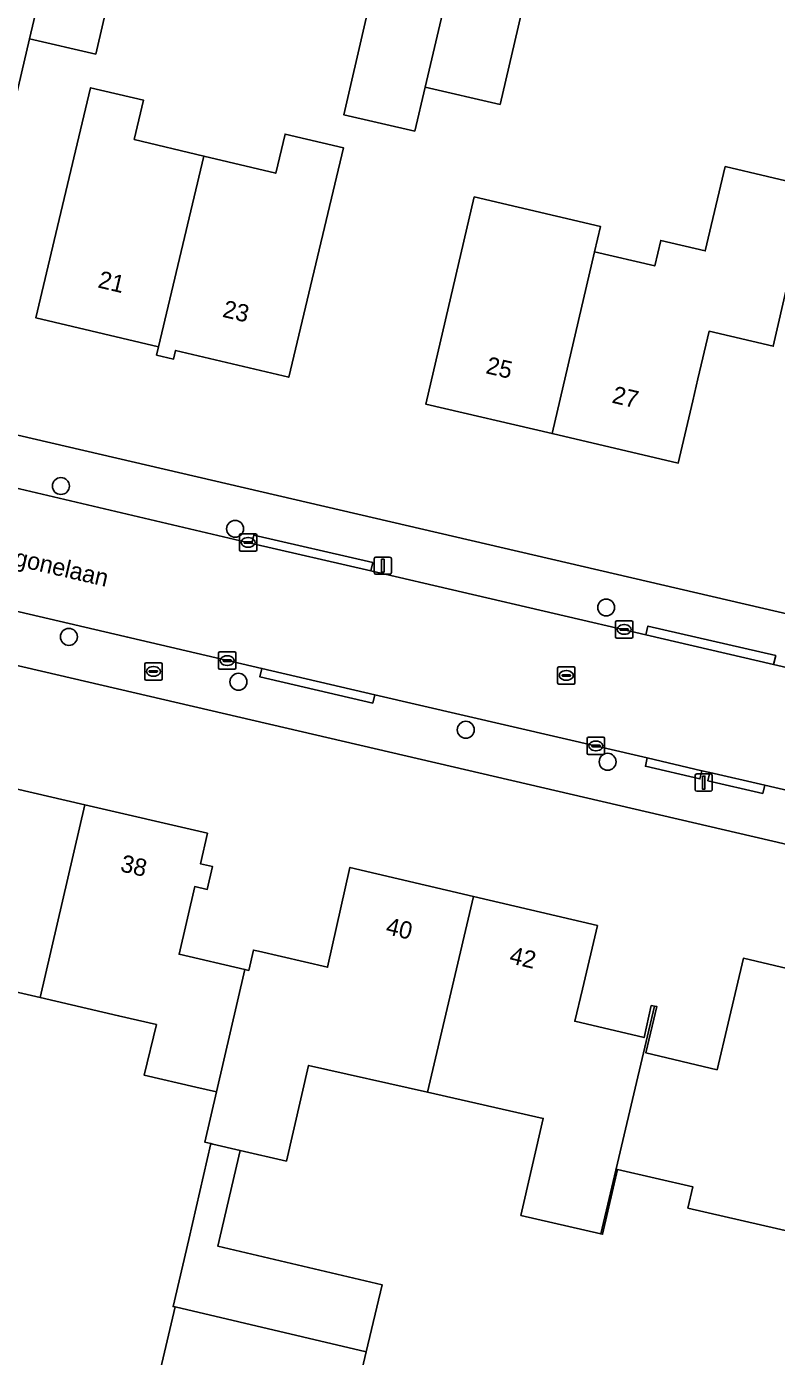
# Model space of a CAD drawing. Extents: x 162184 to 163154, y 385507 to 386516.
# Drawn here: x 162630.3 to 162673.6, y 385878.1 to 385954.9 of the extents above; entities that cross this region are included whole.
import ezdxf

# ---------------------------------------------------------------- set-up
doc = ezdxf.new("R2010")
doc.units = 0
for name, color, linetype in [('IMGEO_Boom', 7, 'Continuous'), ('IMGEO_Brandkraan', 7, 'Continuous'), ('IMGEO_Erf', 7, 'Continuous'), ('IMGEO_Kolk', 7, 'Continuous'), ('IMGEO_Lichtmast', 7, 'Continuous'), ('IMGEO_Openbare_ruimte_label', 7, 'Continuous'), ('IMGEO_Pand', 7, 'Continuous'), ('IMGEO_Pand_nummerreeks', 7, 'Continuous'), ('IMGEO_Rijbaan_lokaal_open', 7, 'Continuous'), ('IMGEO_Rioolput', 7, 'Continuous'), ('IMGEO_Voetpad_open', 7, 'Continuous')]:
    doc.layers.add(name, color=color, linetype=linetype)

msp = doc.modelspace()

# ---------------------------------------------------------------- linework, layer by layer
at = {"layer": 'IMGEO_Boom'}
for centre in [(162632.267, 385928.363), (162642.328, 385925.887), (162663.761, 385921.341), (162632.729, 385919.642), (162642.52, 385917.05), (162655.653, 385914.276), (162663.847, 385912.426)]:
    msp.add_circle(centre, 0.489, dxfattribs=at)
at = {"layer": 'IMGEO_Brandkraan'}
for p, q in [((162637.108, 385917.221), (162637.108, 385918.073)), ((162637.183, 385918.147), (162638.035, 385918.147)), ((162637.367, 385917.641), (162637.367, 385917.653)), ((162637.805, 385917.604), (162637.407, 385917.604)), ((162637.41, 385917.69), (162637.808, 385917.69)), ((162637.596, 385917.927), (162637.621, 385917.927)), ((162637.851, 385917.653), (162637.851, 385917.641)), ((162638.109, 385918.073), (162638.109, 385917.221)), ((162638.035, 385917.147), (162637.183, 385917.147)), ((162637.619, 385917.367), (162637.594, 385917.367))]:
    msp.add_line(p, q, dxfattribs=at)
for points in [[(162637.108, 385917.221), (162637.108, 385918.073)], [(162637.183, 385918.147), (162638.035, 385918.147)], [(162638.109, 385918.073), (162638.109, 385917.221)], [(162638.035, 385917.147), (162637.183, 385917.147)]]:
    msp.add_lwpolyline(points, dxfattribs=at)
for centre, radius, start, end in [((162637.185, 385918.071), 0.0765, 91.55205, 178.44795), ((162637.185, 385918.071), 0.0765, 91.55205, 178.44795), ((162637.407, 385917.65), 0.0403, 85.87752, 175.75265), ((162637.404, 385917.64), 0.0366, 178.93798, 274.71019), ((162637.808, 385917.647), 0.043, 264.86636, 352.45326), ((162637.812, 385917.652), 0.0386, 1.73085, 96.63898), ((162638.033, 385918.071), 0.0765, 1.55205, 88.44795), ((162638.033, 385918.071), 0.0765, 1.55205, 88.44795), ((162637.185, 385917.223), 0.0765, 181.55205, 268.44795), ((162637.185, 385917.223), 0.0765, 181.55205, 268.44795), ((162638.033, 385917.223), 0.0765, 271.55205, 358.44795), ((162638.033, 385917.223), 0.0765, 271.55205, 358.44795)]:
    msp.add_arc(centre, radius, start, end, dxfattribs=at)
for centre, major_axis, ratio, start_param, end_param in [((162637.595, 385917.647), (-0.387, 0.002), 0.722429, 4.712389, 7.853982), ((162637.62, 385917.647), (-0.39, 0.002), 0.717154, 1.570796, 4.712389)]:
    msp.add_ellipse(centre, major_axis=major_axis, ratio=ratio, start_param=start_param, end_param=end_param, dxfattribs=at)
at = {"layer": 'IMGEO_Erf'}
for points in [[(162631.269, 385957.737), (162627.989, 385958.519), (162629.646, 385965.47), (162629.445, 385965.517), (162627.833, 385958.556), (162625.653, 385949.215), (162625.766, 385949.188), (162625.597, 385948.48), (162628.926, 385947.687), (162630.448, 385954.213)], [(162659.52, 385958.55), (162657.637, 385950.422), (162653.306, 385951.425), (162652.706, 385948.878), (162648.607, 385949.827), (162651.08, 385960.505), (162655.219, 385959.546)], [(162677.484, 385954.19), (162683.364, 385952.8), (162682.951, 385951.053), (162682.096, 385951.255), (162680.348, 385943.861), (162681.453, 385943.599), (162681.163, 385942.376), (162675.102, 385943.81), (162673.411, 385936.441), (162669.703, 385937.308), (162669.061, 385934.562), (162668.765, 385933.296), (162667.923, 385929.693), (162660.635, 385931.396), (162653.345, 385933.1), (162654.483, 385937.969), (162656.144, 385945.073), (162663.43, 385943.37), (162663.086, 385941.898), (162666.567, 385941.084), (162666.911, 385942.556), (162669.488, 385941.953), (162670.644, 385946.832), (162675.53, 385945.674)], [(162636.498, 385948.396), (162640.529, 385947.435), (162644.671, 385946.442), (162645.212, 385948.71), (162648.592, 385947.904), (162646.589, 385939.51), (162645.429, 385934.646), (162638.891, 385936.206), (162638.77, 385935.701), (162637.79, 385935.934), (162637.902, 385936.403), (162630.812, 385938.094), (162631.972, 385942.958), (162633.983, 385951.389), (162637.038, 385950.66)]]:
    msp.add_lwpolyline(points, close=True, dxfattribs=at)
for points in [[(162636.708, 385963.834), (162634.274, 385953.326), (162630.448, 385954.213), (162628.926, 385947.687), (162625.597, 385948.48), (162625.226, 385946.922), (162624.067, 385942.058), (162623.062, 385942.297), (162622.522, 385940.031), (162615.44, 385941.718), (162608.362, 385943.404), (162608.894, 385945.636), (162607.824, 385945.892), (162608.983, 385950.756), (162609.465, 385952.777), (162609.699, 385953.758), (162610.448, 385956.905)], [(162535.867, 385953.127), (162747.115, 385904.027), (162750.77, 385903.177)], [(162742.31, 385891.809), (162533.141, 385940.448)], [(162626.577, 385911.571), (162633.653, 385909.93), (162640.729, 385908.289), (162640.321, 385906.529), (162641.027, 385906.365), (162640.72, 385905.041), (162640, 385905.208), (162639.093, 385901.299), (162642.899, 385900.417), (162643.115, 385900.367), (162643.387, 385901.539), (162643.682, 385901.471), (162647.671, 385900.547), (162648.96, 385906.32), (162656.108, 385904.635), (162663.253, 385902.951), (162662.388, 385899.277), (162661.952, 385897.428), (162665.951, 385896.486), (162666.369, 385898.334), (162666.554, 385898.3), (162666.691, 385898.274), (162666.06, 385895.594), (162670.174, 385894.625), (162670.806, 385897.306), (162671.692, 385901.065), (162678.528, 385899.454)], [(162637.027, 385873.14), (162638.858, 385880.909), (162638.747, 385880.935), (162639.646, 385884.81), (162640.931, 385890.354), (162640.584, 385890.435), (162641.257, 385893.337), (162640.064, 385893.614), (162637.082, 385894.305), (162637.783, 385897.233), (162635.601, 385897.739), (162631.071, 385898.789), (162626.359, 385899.882)], [(162674.784, 385885.176), (162668.484, 385886.628), (162668.767, 385887.856), (162664.423, 385888.858), (162663.559, 385885.109), (162663.453, 385885.133), (162658.836, 385886.199), (162660.131, 385891.812), (162653.442, 385893.324), (162646.576, 385894.876), (162645.293, 385889.343), (162642.617, 385889.963), (162641.331, 385884.415), (162650.818, 385882.191), (162649.904, 385878.319), (162648.723, 385873.317)]]:
    msp.add_lwpolyline(points, dxfattribs=at)
at = {"layer": 'IMGEO_Kolk'}
for p, q in [((162642.58, 385924.676), (162642.58, 385925.528)), ((162642.655, 385925.602), (162643.507, 385925.602)), ((162642.882, 385925.145), (162643.28, 385925.145)), ((162643.068, 385925.382), (162643.093, 385925.382)), ((162643.581, 385925.528), (162643.581, 385924.676)), ((162643.507, 385924.602), (162642.655, 385924.602)), ((162642.839, 385925.096), (162642.839, 385925.108)), ((162643.277, 385925.059), (162642.879, 385925.059)), ((162643.091, 385924.822), (162643.066, 385924.822)), ((162643.323, 385925.108), (162643.323, 385925.096)), ((162664.302, 385919.645), (162664.302, 385920.497)), ((162664.377, 385920.571), (162665.229, 385920.571)), ((162665.303, 385920.497), (162665.303, 385919.645)), ((162664.561, 385920.065), (162664.561, 385920.077)), ((162664.999, 385920.028), (162664.601, 385920.028)), ((162664.604, 385920.114), (162665.002, 385920.114)), ((162664.813, 385919.791), (162664.788, 385919.791)), ((162664.79, 385920.351), (162664.815, 385920.351)), ((162665.045, 385920.077), (162665.045, 385920.065)), ((162665.229, 385919.571), (162664.377, 385919.571)), ((162641.374, 385917.846), (162641.374, 385918.698)), ((162641.449, 385918.772), (162642.301, 385918.772)), ((162641.633, 385918.266), (162641.633, 385918.278)), ((162642.071, 385918.229), (162641.673, 385918.229)), ((162641.676, 385918.315), (162642.074, 385918.315)), ((162641.862, 385918.552), (162641.887, 385918.552)), ((162642.117, 385918.278), (162642.117, 385918.266)), ((162642.375, 385918.698), (162642.375, 385917.846)), ((162642.301, 385917.772), (162641.449, 385917.772)), ((162641.885, 385917.992), (162641.86, 385917.992)), ((162662.668, 385912.914), (162662.668, 385913.766)), ((162662.743, 385913.84), (162663.595, 385913.84)), ((162663.156, 385913.62), (162663.181, 385913.62)), ((162663.669, 385913.766), (162663.669, 385912.914)), ((162663.595, 385912.84), (162662.743, 385912.84)), ((162662.927, 385913.334), (162662.927, 385913.346)), ((162663.365, 385913.297), (162662.967, 385913.297)), ((162662.97, 385913.383), (162663.368, 385913.383)), ((162663.179, 385913.06), (162663.154, 385913.06)), ((162663.411, 385913.346), (162663.411, 385913.334))]:
    msp.add_line(p, q, dxfattribs=at)
for points in [[(162642.58, 385924.676), (162642.58, 385925.528)], [(162642.655, 385925.602), (162643.507, 385925.602)], [(162643.581, 385925.528), (162643.581, 385924.676)], [(162643.507, 385924.602), (162642.655, 385924.602)], [(162664.302, 385919.645), (162664.302, 385920.497)], [(162664.377, 385920.571), (162665.229, 385920.571)], [(162665.303, 385920.497), (162665.303, 385919.645)], [(162665.229, 385919.571), (162664.377, 385919.571)], [(162641.374, 385917.846), (162641.374, 385918.698)], [(162641.449, 385918.772), (162642.301, 385918.772)], [(162642.375, 385918.698), (162642.375, 385917.846)], [(162642.301, 385917.772), (162641.449, 385917.772)], [(162662.668, 385912.914), (162662.668, 385913.766)], [(162662.743, 385913.84), (162663.595, 385913.84)], [(162663.669, 385913.766), (162663.669, 385912.914)], [(162663.595, 385912.84), (162662.743, 385912.84)]]:
    msp.add_lwpolyline(points, dxfattribs=at)
for centre, radius, start, end in [((162642.657, 385925.526), 0.0765, 91.55205, 178.44795), ((162642.657, 385925.526), 0.0765, 91.55205, 178.44795), ((162642.879, 385925.105), 0.0403, 85.87752, 175.75265), ((162643.284, 385925.107), 0.0386, 1.73085, 96.63898), ((162643.505, 385925.526), 0.0765, 1.55205, 88.44795), ((162643.505, 385925.526), 0.0765, 1.55205, 88.44795), ((162642.657, 385924.678), 0.0765, 181.55205, 268.44795), ((162642.657, 385924.678), 0.0765, 181.55205, 268.44795), ((162642.876, 385925.095), 0.0366, 178.93798, 274.71019), ((162643.28, 385925.102), 0.043, 264.86636, 352.45326), ((162643.505, 385924.678), 0.0765, 271.55205, 358.44795), ((162643.505, 385924.678), 0.0765, 271.55205, 358.44795), ((162664.379, 385920.495), 0.0765, 91.55205, 178.44795), ((162664.379, 385920.495), 0.0765, 91.55205, 178.44795), ((162665.227, 385920.495), 0.0765, 1.55205, 88.44795), ((162665.227, 385920.495), 0.0765, 1.55205, 88.44795), ((162664.601, 385920.074), 0.0403, 85.87752, 175.75265), ((162664.598, 385920.064), 0.0366, 178.93798, 274.71019), ((162665.002, 385920.071), 0.043, 264.86636, 352.45326), ((162665.006, 385920.076), 0.0386, 1.73085, 96.63898), ((162664.379, 385919.647), 0.0765, 181.55205, 268.44795), ((162664.379, 385919.647), 0.0765, 181.55205, 268.44795), ((162665.227, 385919.647), 0.0765, 271.55205, 358.44795), ((162665.227, 385919.647), 0.0765, 271.55205, 358.44795), ((162641.451, 385918.696), 0.0765, 91.55205, 178.44795), ((162641.451, 385918.696), 0.0765, 91.55205, 178.44795), ((162641.673, 385918.275), 0.0403, 85.87752, 175.75265), ((162641.67, 385918.265), 0.0366, 178.93798, 274.71019), ((162642.074, 385918.272), 0.043, 264.86636, 352.45326), ((162642.078, 385918.277), 0.0386, 1.73085, 96.63898), ((162642.299, 385918.696), 0.0765, 1.55205, 88.44795), ((162642.299, 385918.696), 0.0765, 1.55205, 88.44795), ((162641.451, 385917.848), 0.0765, 181.55205, 268.44795), ((162641.451, 385917.848), 0.0765, 181.55205, 268.44795), ((162642.299, 385917.848), 0.0765, 271.55205, 358.44795), ((162642.299, 385917.848), 0.0765, 271.55205, 358.44795), ((162662.745, 385913.764), 0.0765, 91.55205, 178.44795), ((162662.745, 385913.764), 0.0765, 91.55205, 178.44795), ((162663.593, 385913.764), 0.0765, 1.55205, 88.44795), ((162663.593, 385913.764), 0.0765, 1.55205, 88.44795), ((162662.745, 385912.916), 0.0765, 181.55205, 268.44795), ((162662.745, 385912.916), 0.0765, 181.55205, 268.44795), ((162662.967, 385913.343), 0.0403, 85.87752, 175.75265), ((162662.964, 385913.333), 0.0366, 178.93798, 274.71019), ((162663.368, 385913.34), 0.043, 264.86636, 352.45326), ((162663.372, 385913.345), 0.0386, 1.73085, 96.63898), ((162663.593, 385912.916), 0.0765, 271.55205, 358.44795), ((162663.593, 385912.916), 0.0765, 271.55205, 358.44795)]:
    msp.add_arc(centre, radius, start, end, dxfattribs=at)
for centre, major_axis, ratio, start_param, end_param in [((162643.067, 385925.102), (-0.387, 0.002), 0.722429, 4.712389, 7.853982), ((162643.092, 385925.102), (-0.39, 0.002), 0.717154, 1.570796, 4.712389), ((162664.789, 385920.071), (-0.387, 0.002), 0.722429, 4.712389, 7.853982), ((162664.814, 385920.071), (-0.39, 0.002), 0.717154, 1.570796, 4.712389), ((162641.861, 385918.272), (-0.387, 0.002), 0.722429, 4.712389, 7.853982), ((162641.886, 385918.272), (-0.39, 0.002), 0.717154, 1.570796, 4.712389), ((162663.155, 385913.34), (-0.387, 0.002), 0.722429, 4.712389, 7.853982), ((162663.18, 385913.34), (-0.39, 0.002), 0.717154, 1.570796, 4.712389)]:
    msp.add_ellipse(centre, major_axis=major_axis, ratio=ratio, start_param=start_param, end_param=end_param, dxfattribs=at)
at = {"layer": 'IMGEO_Lichtmast'}
for p, q in [((162650.364, 385923.359), (162650.364, 385924.159)), ((162650.364, 385924.159), (162650.364, 385923.359)), ((162650.464, 385924.259), (162651.254, 385924.259)), ((162651.254, 385924.259), (162650.464, 385924.259)), ((162651.354, 385924.159), (162651.354, 385923.359)), ((162651.354, 385923.359), (162651.354, 385924.159)), ((162651.254, 385923.259), (162650.464, 385923.259)), ((162650.464, 385923.259), (162651.254, 385923.259)), ((162668.899, 385910.822), (162668.899, 385911.622)), ((162668.899, 385911.622), (162668.899, 385910.822)), ((162668.999, 385911.722), (162669.789, 385911.722)), ((162669.789, 385911.722), (162668.999, 385911.722)), ((162669.889, 385911.622), (162669.889, 385910.822)), ((162669.889, 385910.822), (162669.889, 385911.622)), ((162669.789, 385910.722), (162668.999, 385910.722)), ((162668.999, 385910.722), (162669.789, 385910.722))]:
    msp.add_line(p, q, dxfattribs=at)
for points in [[(162650.784, 385924.134), (162650.934, 385924.134), (162650.934, 385923.384), (162650.784, 385923.384), (162650.784, 385924.134)], [(162669.319, 385911.597), (162669.469, 385911.597), (162669.469, 385910.847), (162669.319, 385910.847), (162669.319, 385911.597)]]:
    msp.add_lwpolyline(points, dxfattribs=at)
for centre, start, end in [((162650.464, 385924.159), 90, 180), ((162650.464, 385924.159), 90, 180), ((162651.254, 385924.159), 0, 90), ((162651.254, 385924.159), 360, 90), ((162650.464, 385923.359), 180, 270), ((162650.464, 385923.359), 180, 270), ((162651.254, 385923.359), 270, 0), ((162651.254, 385923.359), 270, 0), ((162668.999, 385911.622), 90, 180), ((162668.999, 385911.622), 90, 180), ((162669.789, 385911.622), 0, 90), ((162669.789, 385911.622), 360, 90), ((162668.999, 385910.822), 180, 270), ((162668.999, 385910.822), 180, 270), ((162669.789, 385910.822), 270, 0), ((162669.789, 385910.822), 270, 0)]:
    msp.add_arc(centre, 0.1, start, end, dxfattribs=at)
at = {"layer": 'IMGEO_Pand'}
for points in [[(162636.708, 385963.834), (162632.896, 385964.717), (162631.269, 385957.737), (162630.448, 385954.213), (162634.274, 385953.326)], [(162655.219, 385959.546), (162651.08, 385960.505), (162648.607, 385949.827), (162652.706, 385948.878), (162653.306, 385951.425)], [(162653.306, 385951.425), (162657.637, 385950.422), (162659.52, 385958.55), (162655.219, 385959.546)], [(162640.529, 385947.435), (162636.498, 385948.396), (162637.038, 385950.66), (162633.983, 385951.389), (162631.972, 385942.958), (162630.812, 385938.094), (162637.902, 385936.403)], [(162648.592, 385947.904), (162645.212, 385948.71), (162644.671, 385946.442), (162640.529, 385947.435), (162637.902, 385936.403), (162637.79, 385935.934), (162638.77, 385935.701), (162638.891, 385936.206), (162645.429, 385934.646), (162646.589, 385939.51)], [(162675.102, 385943.81), (162675.53, 385945.674), (162670.644, 385946.832), (162669.488, 385941.953), (162666.911, 385942.556), (162666.567, 385941.084), (162663.086, 385941.898), (162660.635, 385931.396), (162667.923, 385929.693), (162668.765, 385933.296), (162669.061, 385934.562), (162669.703, 385937.308), (162673.411, 385936.441)], [(162663.086, 385941.898), (162663.43, 385943.37), (162656.144, 385945.073), (162654.483, 385937.969), (162653.345, 385933.1), (162660.635, 385931.396)], [(162633.653, 385909.93), (162626.577, 385911.571), (162624.926, 385904.453), (162620.737, 385905.424), (162618.781, 385896.952), (162623.047, 385895.963), (162624.078, 385900.411), (162626.359, 385899.882), (162631.071, 385898.789)], [(162633.653, 385909.93), (162631.071, 385898.789), (162635.601, 385897.739), (162637.783, 385897.233), (162637.082, 385894.305), (162640.064, 385893.614), (162641.257, 385893.337), (162642.899, 385900.417), (162639.093, 385901.299), (162640, 385905.208), (162640.72, 385905.041), (162641.027, 385906.365), (162640.321, 385906.529), (162640.729, 385908.289)], [(162656.108, 385904.635), (162648.96, 385906.32), (162647.671, 385900.547), (162643.682, 385901.471), (162643.387, 385901.539), (162643.115, 385900.367), (162642.899, 385900.417), (162641.257, 385893.337), (162640.584, 385890.435), (162640.931, 385890.354), (162641.045, 385890.328), (162642.617, 385889.963), (162645.293, 385889.343), (162646.576, 385894.876), (162653.442, 385893.324)], [(162662.388, 385899.277), (162663.253, 385902.951), (162656.108, 385904.635), (162653.442, 385893.324), (162660.131, 385891.812), (162658.836, 385886.199), (162663.453, 385885.133), (162666.554, 385898.3), (162666.369, 385898.334), (162665.951, 385896.486), (162661.952, 385897.428)], [(162666.691, 385898.274), (162666.554, 385898.3), (162663.453, 385885.133), (162663.559, 385885.109), (162664.423, 385888.858), (162668.767, 385887.856), (162668.484, 385886.628), (162674.784, 385885.176), (162675.796, 385889.561), (162676.177, 385889.473), (162678.528, 385899.454), (162671.692, 385901.065), (162670.806, 385897.306), (162670.174, 385894.625), (162666.06, 385895.594)], [(162650.818, 385882.191), (162641.331, 385884.415), (162642.617, 385889.963), (162641.045, 385890.328), (162640.931, 385890.354), (162639.646, 385884.81), (162638.747, 385880.935), (162638.858, 385880.909), (162649.904, 385878.319)], [(162637.027, 385873.14), (162640.961, 385872.21), (162641.619, 385874.994), (162648.723, 385873.317), (162649.904, 385878.319), (162638.858, 385880.909)]]:
    msp.add_lwpolyline(points, close=True, dxfattribs=at)
at = {"layer": 'IMGEO_Rijbaan_lokaal_open'}
for points in [[(162746.173, 385901.16), (162714.497, 385908.493), (162710.912, 385909.327), (162696.525, 385912.674), (162693.099, 385913.471), (162692.049, 385913.715), (162688.508, 385914.539), (162673.435, 385918.045), (162666.053, 385919.762), (162650.169, 385923.455), (162643.294, 385925.05), (162628.553, 385928.5)], [(162628.35, 385921.436), (162643.88, 385917.817), (162650.397, 385916.299), (162666.138, 385912.642), (162669.29, 385911.909), (162669.754, 385911.801), (162672.921, 385911.065), (162689.469, 385907.22), (162692.571, 385906.5), (162702.638, 385904.161), (162706.317, 385903.306), (162706.904, 385903.169), (162713.499, 385901.637), (162743.872, 385894.504)]]:
    msp.add_lwpolyline(points, dxfattribs=at)
at = {"layer": 'IMGEO_Rioolput'}
for p, q in [((162660.96, 385916.988), (162660.96, 385917.84)), ((162661.035, 385917.914), (162661.887, 385917.914)), ((162661.262, 385917.457), (162661.66, 385917.457)), ((162661.448, 385917.694), (162661.473, 385917.694)), ((162661.961, 385917.84), (162661.961, 385916.988)), ((162661.887, 385916.914), (162661.035, 385916.914)), ((162661.219, 385917.408), (162661.219, 385917.42)), ((162661.657, 385917.371), (162661.259, 385917.371)), ((162661.471, 385917.134), (162661.446, 385917.134)), ((162661.703, 385917.42), (162661.703, 385917.408))]:
    msp.add_line(p, q, dxfattribs=at)
for points in [[(162660.96, 385916.988), (162660.96, 385917.84)], [(162661.035, 385917.914), (162661.887, 385917.914)], [(162661.961, 385917.84), (162661.961, 385916.988)], [(162661.887, 385916.914), (162661.035, 385916.914)]]:
    msp.add_lwpolyline(points, dxfattribs=at)
for centre, radius, start, end in [((162661.037, 385917.838), 0.0765, 91.55205, 178.44795), ((162661.037, 385917.838), 0.0765, 91.55205, 178.44795), ((162661.259, 385917.417), 0.0403, 85.87752, 175.75265), ((162661.664, 385917.419), 0.0386, 1.73085, 96.63898), ((162661.885, 385917.838), 0.0765, 1.55205, 88.44795), ((162661.885, 385917.838), 0.0765, 1.55205, 88.44795), ((162661.037, 385916.99), 0.0765, 181.55205, 268.44795), ((162661.037, 385916.99), 0.0765, 181.55205, 268.44795), ((162661.256, 385917.407), 0.0366, 178.93798, 274.71019), ((162661.66, 385917.414), 0.043, 264.86636, 352.45326), ((162661.885, 385916.99), 0.0765, 271.55205, 358.44795), ((162661.885, 385916.99), 0.0765, 271.55205, 358.44795)]:
    msp.add_arc(centre, radius, start, end, dxfattribs=at)
for centre, major_axis, ratio, start_param, end_param in [((162661.447, 385917.414), (-0.387, 0.002), 0.722429, 4.712389, 7.853982), ((162661.472, 385917.414), (-0.39, 0.002), 0.717154, 1.570796, 4.712389)]:
    msp.add_ellipse(centre, major_axis=major_axis, ratio=ratio, start_param=start_param, end_param=end_param, dxfattribs=at)
at = {"layer": 'IMGEO_Voetpad_open'}
for points in [[(162750.77, 385903.177), (162747.115, 385904.027), (162535.867, 385953.127)], [(162533.141, 385940.448), (162742.31, 385891.809)], [(162628.553, 385928.5), (162643.294, 385925.05), (162643.405, 385925.531), (162650.281, 385923.942), (162650.169, 385923.455), (162666.053, 385919.762), (162666.17, 385920.268), (162673.555, 385918.56), (162673.435, 385918.045), (162688.508, 385914.539), (162688.632, 385915.068), (162692.173, 385914.242), (162692.049, 385913.715), (162693.099, 385913.471), (162693.222, 385913.998), (162696.647, 385913.199), (162696.525, 385912.674), (162710.912, 385909.327), (162711.033, 385909.845), (162714.618, 385909.008), (162714.497, 385908.493), (162746.173, 385901.16)], [(162689.469, 385907.22), (162672.921, 385911.065), (162672.811, 385910.595), (162669.643, 385911.329), (162669.754, 385911.801), (162669.29, 385911.909), (162669.179, 385911.436), (162666.026, 385912.166), (162666.138, 385912.642), (162650.397, 385916.299), (162650.28, 385915.814), (162643.761, 385917.324), (162643.88, 385917.817), (162628.35, 385921.436)]]:
    msp.add_lwpolyline(points, dxfattribs=at)
for points in [[(162650.169, 385923.455), (162650.281, 385923.942), (162643.405, 385925.531), (162643.294, 385925.05)], [(162666.053, 385919.762), (162673.435, 385918.045), (162673.555, 385918.56), (162666.17, 385920.268)], [(162643.88, 385917.817), (162643.761, 385917.324), (162650.28, 385915.814), (162650.397, 385916.299)], [(162669.29, 385911.909), (162666.138, 385912.642), (162666.026, 385912.166), (162669.179, 385911.436)], [(162669.754, 385911.801), (162669.643, 385911.329), (162672.811, 385910.595), (162672.921, 385911.065)]]:
    msp.add_lwpolyline(points, close=True, dxfattribs=at)

# ---------------------------------------------------------------- texts
at = {"layer": 'IMGEO_Openbare_ruimte_label'}
msp.add_text('Antigonelaan', height=1, rotation=346.88086, dxfattribs=at).set_placement((162627.27, 385924.306))
at = {"layer": 'IMGEO_Pand_nummerreeks'}
for s, rotation, p in [('21', 346.72457, (162634.35, 385939.85)), ('23', 346.72457, (162641.549, 385938.151)), ('25', 346.84489, (162656.758, 385934.89)), ('27', 346.84489, (162664.047, 385933.187)), ('38', 346.94229, (162635.648, 385906.1)), ('40', 346.73603, (162650.979, 385902.475)), ('42', 346.73692, (162658.12, 385900.791))]:
    msp.add_text(s, height=1, rotation=rotation, dxfattribs=at).set_placement(p)

doc.saveas('drawing.dxf')
